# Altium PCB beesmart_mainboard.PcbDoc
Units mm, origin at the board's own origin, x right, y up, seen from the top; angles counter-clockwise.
Board outline 27.5 x 70 mm, 2 copper layers (Top Layer, Bottom Layer); 29 components, 23 nets, 160 pads, 144 vias.
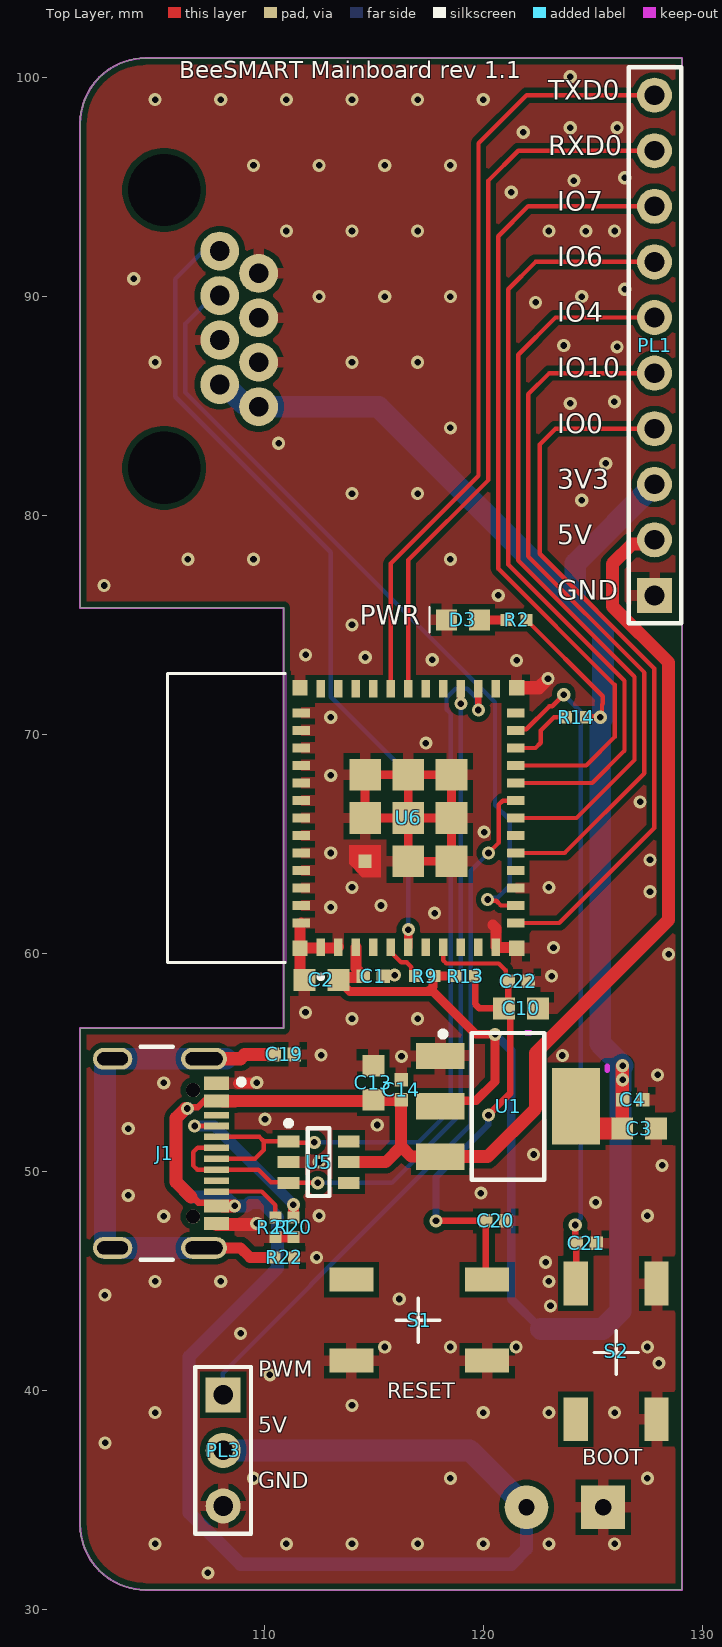
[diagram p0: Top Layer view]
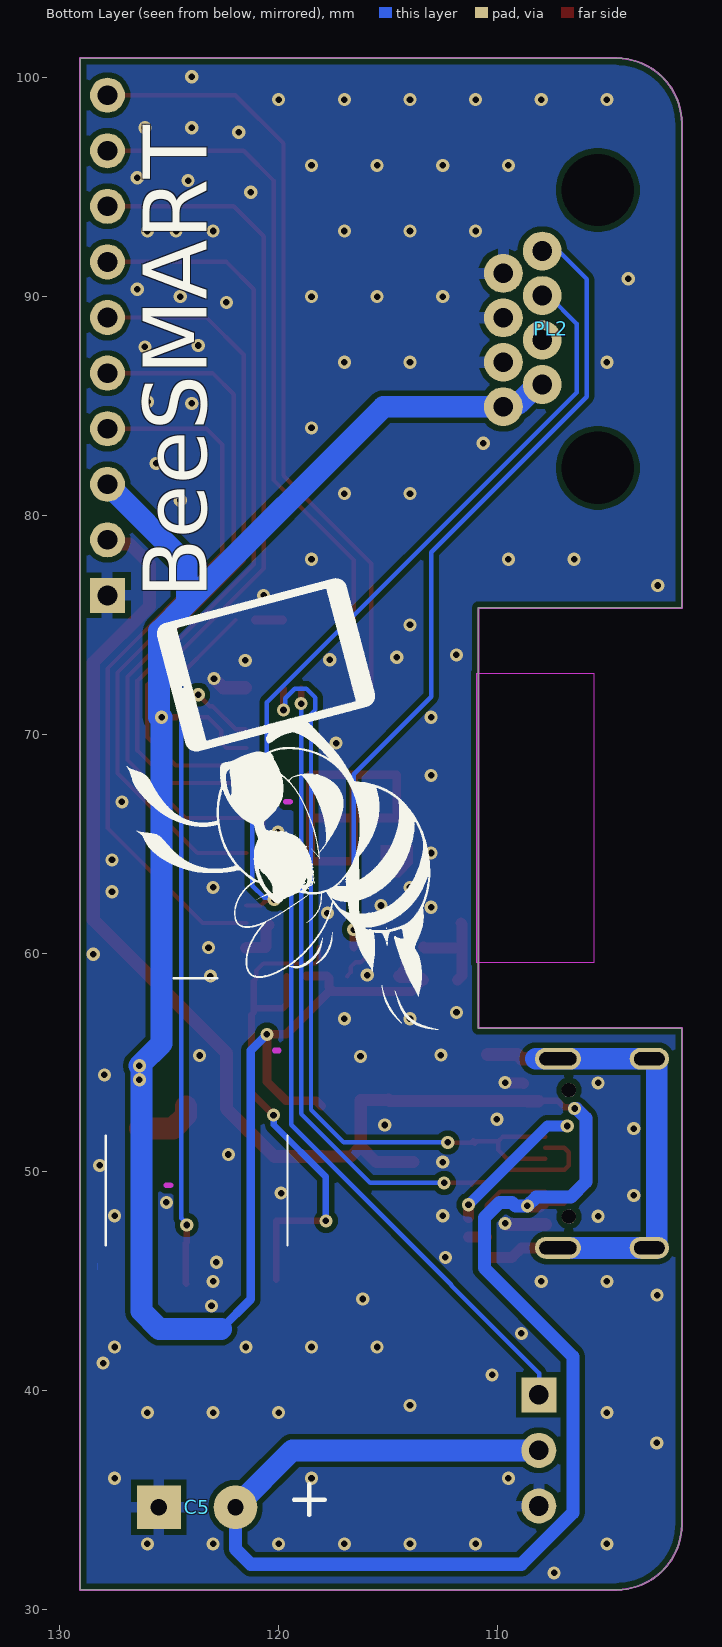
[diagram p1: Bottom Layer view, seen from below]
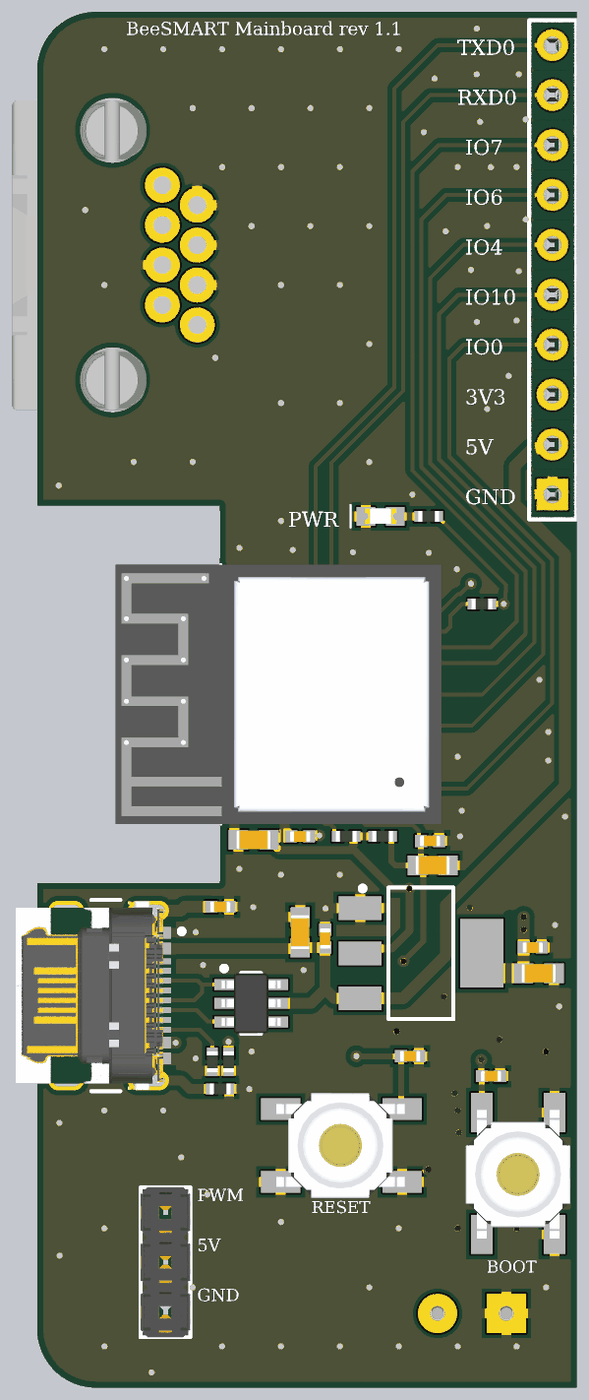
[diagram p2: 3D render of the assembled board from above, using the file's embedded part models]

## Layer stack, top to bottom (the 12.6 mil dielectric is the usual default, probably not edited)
Top Solder: solder mask 0.0102, Solder Resist, Dk 3.5
Top Layer: signal copper 0.0356
Dielectric 1: dielectric 0.32, FR-4, Dk 4.8
Bottom Layer: signal copper 0.0356
Bottom Solder: solder mask 0.0102, Solder Resist, Dk 3.5

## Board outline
101.575,33.9 101.575,56.575 110.875,56.575 110.875,75.775 101.575,75.775 101.575,97.9 cw(c104.575,97.9) 104.575,100.9 129.075,100.9 129.075,30.9 104.575,30.9 cw(c104.575,33.9)

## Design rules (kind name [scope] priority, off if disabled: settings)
Clearance [All] p1: gap=0.254 ignorepadtopadclearanceinfootprint=FALSE except(0: Arc-Hole Track-Hole SMDPad-Hole THPad-Hole Via-Hole Fill-Hole Poly-Hole Region-Hole Text-Hole; 0.2: Arc-SMDPad Arc-THPad Track-SMDPad Track-THPad SMDPad-SMDPad SMDPad-THPad)
PlaneConnect [All] p1: planeconnectstyle=Relief reliefexpansion=0.508 reliefentries=4 reliefconductorwidth=0.5 reliefairgap=0.254
PolygonConnect PolygonConnect_2 [IsVia] p1: connectstyle=Direct reliefconductorwidth=0.254 reliefentries=4 polygonreliefangle="90 Angle" airgapwidth=0.254
PolygonConnect PolygonConnect_1 [(InNet('VBUS') OR InNet('NetF1_2'))] p2: connectstyle=Direct reliefconductorwidth=0.254 reliefentries=4 polygonreliefangle="90 Angle" airgapwidth=0.254
PolygonConnect [All] p3: connectstyle=Relief reliefconductorwidth=0.5 reliefentries=4 polygonreliefangle="90 Angle" airgapwidth=0.254
RoutingVias [All] p1: holewidth=0.711 width=1.27 viastyle="Through Hole" minholewidth=0.711 minwidth=1.27 maxholewidth=0.711 maxwidth=1.27
SolderMaskExpansion [All] p1: expansion=0.102 istentingtop=FALSE
Width [All] p1: maxlimit=1 minlimit=0.2 preferedwidth=0.25 minimp=50.000000 maximp=50.000000 favimp=50.000000
29 further rules are at their usual default settings.

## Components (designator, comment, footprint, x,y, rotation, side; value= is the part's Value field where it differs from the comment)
C1 "0.1uF 0402 10V" CAP_0402 114.975,58.95 r180 top value="100 nF"
C2 "22uF 0603" CAP_0603 112.6,58.775 r0 top value=22uF
C3 "22uF 0603" CAP_0603 127.125,51.984 r180 top value=22uF
C4 "0.1uF 0402 10V" CAP_0402 126.825,53.3 r180 top value="100 nF"
C5 "180uF" "Capacitor 8x22" 123.725,34.675 r180 bottom
C10 "22uF 0603" CAP_0603 121.725,57.475 r180 top value=22uF
C13 "22uF 0603" CAP_0603 114.975,54.075 r270 top value=22uF
C14 "0.1uF 0402 10V" CAP_0402 116.25,53.75 r270 top value="100 nF"
C19 "47pF 0402 50V" CAP_0402 110.906,55.367 r180 top value=47pF
C20 "0.1uF 0402 10V" CAP_0402 120.575,47.763 r180 top value="100 nF"
C21 "0.1uF 0402 10V" CAP_0402 124.7,46.75 r180 top value="100 nF"
C22 "0.1uF 0402 10V" CAP_0402 121.591,58.716 r0 top value="100 nF"
D3 "GREEN LED 0603" "0603 LED" 103.069,68.24 r0 top
J1 "USB4105-GF-A" FP-USB4105-GF-A-MFG 104.225,50.85 r270 top
PL1 "10-pin Male Header 2.54mm" "10-pin 2.54mm header" 127.825,87.775 r90 top
PL2 "RJHSE-5080/R-RJ45R08P-A004" "AMPHENOL RJHSE-5080" 107.575,88.525 r90 bottom
PL3 "3-pin 2.54mm" "3-pin 2.54mm header" 108.112,37.275 r270 top
R2 "1k 0402" RES_0402 121.521,75.225 r0 top value=1k
R9 "10k 0.5% 0402" RES_0402 117.325,58.95 r0 top value=10k
R13 "10k 0.5% 0402" RES_0402 119.175,58.95 r180 top value=10k
R14 "10k 0.5% 0402" RES_0402 124.24,70.779 r0 top value=10k
R20 "4k7 0402" RES_0402 111.325,47.475 r90 top value=4k7
R21 "4k7 0402" RES_0402 110.5,47.475 r90 top value=4k7
R22 "1MOhm 0402 5%" RES_0402 110.9,46.1 r180 top value=1Mega
S1 "TACTB-64K-F" TACTB-64K-F 117.075,43.225 r0 top
S2 "TACTB-64K-F" TACTB-64K-F 126.075,41.8 r90 top
U1 "3.3V LDO 1A" SOT230P700X180-4N 121.131,53 r0 top
U5 "SRV05-" SOT95P280X145-6N 112.475,50.45 r0 top
U6 "ESP32-C3-MINI-1-N4" ESP32-C3-MINI-1-N4-Footprint-1 113.875,66.175 r90 top locked

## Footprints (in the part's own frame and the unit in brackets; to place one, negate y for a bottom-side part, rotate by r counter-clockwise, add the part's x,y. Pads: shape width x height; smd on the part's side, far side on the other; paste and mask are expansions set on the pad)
"3-pin 2.54mm header" [mm]
  rect 1.6x1.6 hole 0.9: 1(-2.54,0)
  round 1.6 hole 0.9: 2(0,0) 3(2.54,0)
  silkscreen extent -3.81,-1.27 3.81,1.27, body extent -3.81,-1.27 3.81,1.27, height 9.5
"10-pin 2.54mm header" [mm]
  rect 1.6x1.6 hole 0.9: 1(-11.43,0)
  round 1.6 hole 0.9: 2(-8.89,0) 3(-6.35,0) 4(-3.81,0) 5(-1.27,0) 6(1.27,0) 7(3.81,0) 8(6.35,0) 9(8.89,0) 10(11.43,0)
  silkscreen extent -12.7,-1.22 12.7,1.18, body extent -12.7,-1.24 12.7,1.25, height 8.54
"0603 LED" [mm] "0603 LED"
  rect 0.95x0.95 smd: 1(16.752,6.985) 2(15.252,6.985)
  silkscreen extent 14.48,6.43 14.48,7.57, body extent 15.2,6.61 16.8,7.39, height 0.7
"AMPHENOL RJHSE-5080" [mil] "RJ45 connector"
  round 0 hole 130 unplated: 0(-250,-85) 0(250,-85)
  round 70 hole 35.43: 1(140,15) 2(100,85) 3(60,15) 4(20,85) 5(-20,15) 6(-60,85) 7(-100,15) 8(-140,85)
  body extent -310,-286 310,304, height 521
CAP_0402 [mm] "Chip Capacitor, 2-Leads, 0402, IPC Medium Density"
  rect 0.62x0.62 smd: 1(-0.46,0) 2(0.46,0)
  body extent -0.53,-0.28 0.53,0.28, height 0.4
CAP_0603 [mm] "Chip Capacitor, 2-Leads, 0603, IPC Medium Density"
  rect 1x1 smd: 1(-0.775,0) 2(0.775,0)
  body extent -0.87,-0.48 0.87,0.48, height 0.55
"Capacitor 8x22" [mm]
  round 2 hole 0.75: 1(1.75,0)
  rect 2x2 hole 0.75: 2(-1.75,0)
  silkscreen extent -4.18,-0.35 5.82,24.18, body extent -4,-0.3 4,24, height 8.1
ESP32-C3-MINI-1-N4-Footprint-1 [mm]
  rect 0.8x0.4 smd: 1(-5.9,1.3) 2(-5.9,0.5) 3(-5.9,-0.3) 4(-5.9,-1.1) 5(-5.9,-1.9) 6(-5.9,-2.7) 7(-5.9,-3.5) 8(-5.9,-4.3) 9(-5.9,-5.1) 10(-5.9,-5.9) 11(-5.9,-6.7) 25(5.9,-6.7) 26(5.9,-5.9) 27(5.9,-5.1) 28(5.9,-4.3) 29(5.9,-3.5) 30(5.9,-2.7) 31(5.9,-1.9) 32(5.9,-1.1) 33(5.9,-0.3) 34(5.9,0.5) 35(5.9,1.3)
  rect 0.4x0.8 smd: 12(-4.8,-7.6) 13(-4,-7.6) 14(-3.2,-7.6) 15(-2.4,-7.6) 16(-1.6,-7.6) 17(-0.8,-7.6) 18(0,-7.6) 19(0.8,-7.6) 20(1.6,-7.6) 21(2.4,-7.6) 22(3.2,-7.6) 23(4,-7.6) 24(4.8,-7.6) 36(4.8,2.2) 37(4,2.2) 38(3.2,2.2) 39(2.4,2.2) 40(1.6,2.2) 41(0.8,2.2) 42(0,2.2) 43(-0.8,2.2) 44(-1.6,2.2) 45(-2.4,2.2) 46(-3.2,2.2) 47(-4,2.2) 48(-4.8,2.2)
  rect 0.6x0.6 smd paste-1 mask+0: 49_1(-1.975,-0.725)
  rect 1.45x1.45 smd: 49_2(0,-0.725) 49_3(1.975,-0.725) 49_4(1.975,-2.7) 49_5(1.975,-4.675) 49_6(0,-4.675) 49_7(-1.975,-4.675) 49_8(-1.975,-2.7) 49_9(0,-2.7)
  rect 0.7x0.7 smd: 50(5.95,2.25) 51(5.95,-7.65) 52(-5.95,-7.65) 53(-5.95,2.25)
  Top Layer region: -1.25,-1.45 -2.7,-1.45 -2.7,-0.6 -2.1,0 -1.25,0
  Keep-Out Layer region: 6.6,2.9 -6.6,2.9 -6.6,8.3 6.6,8.3
  Keep-Out Layer region: 6.6,2.9 -6.6,2.9 -6.6,8.3 6.6,8.3
  silkscreen extent -7.35,1.2 6.6,8.3, body extent -6.6,-8.3 6.6,8.3, height 2.55
FP-USB4105-GF-A-MFG [mm]
  rrect100% 1x2.1 hole 1.7 slot 0.6 at 0 deg paste-1000 mask+0: 1(-4.32,3.015) 2(4.32,3.015)
  rrect100% 1x1.8 hole 1.4 slot 0.6 at 0 deg paste-1000 mask+0: 3(-4.32,-1.165) 4(4.32,-1.165)
  round 0.65 hole 0.65 unplated paste-1000 mask+0: -(2.89,2.515) --(-2.89,2.515)
  rect 0.6x1.15 smd paste+0 mask+0: A1-B12(-3.2,3.59) A4-B9(-2.4,3.59) B1-A12(3.2,3.59) B4-A9(2.4,3.59)
  rect 0.3x1.15 smd paste+0 mask+0: A5(-1.25,3.59) A6(-0.25,3.59) A7(0.25,3.59) A8(1.25,3.59) B5(1.75,3.59) B6(0.75,3.59) B7(-0.75,3.59) B8(-1.75,3.59)
  silkscreen extent -4.86,0.11 4.86,4.84, body extent -4.96,-3.94 4.96,4.27, height 0.25
RES_0402 [mm] "Chip Resistor, 2-Leads, 0402, IPC Medium Density"
  rect 0.55x0.55 smd: 1(-0.45,0) 2(0.45,0)
  body extent -0.53,-0.28 0.53,0.28, height 0.4
SOT95P280X145-6N [mm] "SOT23, 6-Leads, Body 2.93x2.80mm, Pitch 0.95mm, IPC Medium Density"
  rect 1x0.55 smd: 1(-1.375,0.95) 2(-1.375,0) 3(-1.375,-0.95) 4(1.375,-0.95) 5(1.375,0) 6(1.375,0.95)
  silkscreen extent -1.5,-1.55 0.5,1.9, body extent -1.5,-1.53 1.5,1.53, height 1.45
SOT230P700X180-4N [mm] "SOT223, 4-Leads, Body 6,50x7,00mm (avg), Pitch 2,30mm, IPC Medium Density"
  rect 2.2x1.2 smd: 1(-3.1,2.3) 2(-3.1,0) 3(-3.1,-2.3)
  rect 2.2x3.5 smd: 2(3.1,0)
  silkscreen extent -3.1,-3.35 1.65,3.42, body extent -1.85,-3.35 1.85,3.35, height 1.8
TACTB-64K-F [mm] "Tactile switch"
  rect 2x1.1 smd: 1(-3.1,1.85) 2(3.1,1.85) 3(-3.1,-1.85) 4(3.1,-1.85)
  silkscreen extent -1.05,-1 0.95,1, body extent -3.32,-2.67 3.23,2.68, height 1.6

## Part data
C1 C4 C14 C20 C21 C22: library part CMP-00101-1, "0.1uF 0402 10V X7R 10%", Tolerance="10 %", Voltage="10 V"
C2 C3 C10 C13: library part CMP-00148-1, "Cap Ceramic 22uF 6.3V X5R 20% SMD 0603 85C Cardboard T/R", Capacitance=22uF, Case Code (Imperial)=0603, Case Code (Metric)=1608, Dielectric=X5R, Max Operating Temperature=85°C, Min Operating Temperature=-55°C, Package Quantity=1, Tolerance=20%, Voltage=6.3V
C5: library part CMP-002-0002-4, "CAP ALUM 180UF 20% 50V RADIAL", Case/Package=-, Mfg. Part Number=EEU-FR1H181LB, Tolerance=20%, Voltage=50V
C19: library part CMP-00099-1, "47pF 0402 50V X7R 5%", Tolerance=10%, Voltage=50V
D3: library part CMP-008-0000-1, "SMD GREEN WATER CLEAR", Mfg. Part Number=APT1608SGC
J1: library part CMP-003-0034-0.0, "Conn USB 2.0 Type C RCP 24 POS 0.3mm/0.5mm Solder RA SMD 24 Terminal 1 Port T/R", Flammability Rating="UL94 V-0", Insulation Color=Black, Max Operating Temperature=85°C, Min Operating Temperature=-40°C
PL1: library part CMP-003-0020-0.0, "10 Positions Header Connector 0.100\" (2.54mm) Through Hole Gold"
PL2: library part CMP-003-0022-0.1, "CONN MOD JACK 8P8C R/A UNSHLD", Colour=Black, Contact Resistance=20mR, Current Rating=1.5A, Flammability Rating="UL94 V-0", Max Operating Temperature=85°C, Max Voltage Rating (AC)=125V, Min Operating Temperature=-55°C, Package Quantity=36
PL3: library part CMP-003-0018-1, "Pin header 3-pin 2.54mm male", Mfg. Part Number=DS1021-1*3SF1-1
R2: library part CMP-001-0025-3, "RES SMD 1K OHM 1% 1/16W 0402", Case/Package=0402, Mfg. Part Number=CRG0402F1K0, Power=1/16W, Tolerance=1%
R9 R13 R14: library part CMP-0001-00029-2, "RES 10K OHM 0.5% 1/16W 0402", Case/Package=0402, Manufacturer Part No.=RC0402DR-0710KL, Tolerance=0.5%
R20 R21: library part CMP-001-0029-3, "RES SMD 4.7K OHM 1% 1/16W 0402", Case/Package=0402, Mfg. Part Number=RC1005F472CS, Power=1/16W, Tolerance=1
R22: library part CMP-001-0065-1, "RES SMD 1M OHM 5% 1/16W 0402", Case/Package=0402, Mfg. Part Number=CR0402JC1MS001, Power="1/16 W", Tolerance=5%
S1 S2: library part CMP-013-0002-1, "Microswitch TACT; SPST-NO; Positions:2; 0.05A/12VDC;", Case/Package=-
U1: library part CMP-00114-2, "IC REG LINEAR 3.3V 1A SOT223", Case/Package=TO-261-4, Dropout Voltage=1.1V, Max Input Voltage=13V, Max Operating Temperature=125°C, Max Output Current=1A, Min Operating Temperature=-40°C, Operating Supply Current=3.5mA, Output Voltage=3.3V, Package Quantity=4000, Power Supply Rejection Ratio (PSRR)=70dB, Reference Voltage=1.262V
U5: library part CMP-016-0020-1, "SRV05 Series 4 Ch 3.5 pF 15 Vclamp Steering Diode/TVS Array Combo - SOT-23-6", Capacitance=3.5pF, Case/Package=SOT-23, Clamping Voltage=15V, Leakage Current=5uA, Max Operating Temperature=150°C, Min Operating Temperature=-55°C, Peak Pulse Current=5A, Peak Pulse Power=500W, Reverse Breakdown Voltage=6V, Reverse Standoff Voltage=5V, Test Current=1mA
U6: library part CMP-00162-1, "Bluetooth, WiFi 802.11b/g/n, Bluetooth v5.0 Transceiver Module 2.412GHz ~ 2.484GHz PCB Trace Surface Mount"

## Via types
v1: diameter 0.6, hole 0.3, Top Layer to Bottom Layer, tented both sides, 144 vias

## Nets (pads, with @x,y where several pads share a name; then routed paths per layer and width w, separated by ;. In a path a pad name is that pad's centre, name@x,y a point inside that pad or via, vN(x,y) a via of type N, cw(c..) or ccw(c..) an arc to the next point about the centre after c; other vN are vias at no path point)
3V3: C1.2 C2.2 C3.2 C4.2 PL1.3 PL2.7 PL2.8 R2.2 R9.2 R13.2 R14.2 U1.2 U6.3 | length 109
  Top Layer w0.2: R2.2 125.463,71.733 125.463,71.403 125.424,71.364 125.424,70.856 v1(125.347,70.779)
  Top Layer w0.3: R14.2 v1(125.347,70.779)
  Top Layer w0.4: C2.2 113.91,58.24 117.466,58.24 ; U1.2@118.031,53 118.281,53.25 119.661,53.25 120.537,54.126 v1(120.537,56.289) 119.661,56.289 117.71,58.24 117.466,58.24 ; R13.2 R9.2 117.7,58.875 117.7,58.474 117.466,58.24
  Top Layer w0.5: C2.2 113.49,58.89 114.455,58.89 C1.2 114.175,59.29 U6.3
  Top Layer w0.6: C3.2 126.35,54.835 v1(126.365,54.85)
  Top Layer w1: U1.2@124.231,53 124.231,52.584 124.831,51.984 C3.2
  Bottom Layer w0.4: v1(120.537,56.289) 121.275,55.551 121.275,44.182 122.637,42.82
  Bottom Layer w1: PL2.7 108.167,85.985 109.034,85.118 109.585,85.118 PL2.8 115.206,84.969 124.2,75.975 ; 122.637,42.82 125.445,42.82 126.275,43.65 v1@126.275,54.85 ; v1(125.347,70.779) 125.347,55.868 v1(126.365,54.85) ; v1@125.463,70.779 125.463,74.712 124.2,75.975 ; PL1.3 124.2,77.8 124.2,75.975
  other v1: 126.365,54.21
D+: J1.A6 J1.B6 U5.3 U6.27 | length 35.2
  Top Layer w0.2: J1.A6 106.945,51.1 106.74,50.895 106.74,50.297 106.937,50.1 J1.B6 108.815,50.1 108.818,50.103 109.722,50.103 110.3,49.525 111.075,49.525 U5.3 ; U5.3@111.187,49.413 U5.3 ; v1(112.437,49.5) U5.3
  Top Layer w0.3: v1(118.975,71.4) U6.27
  Bottom Layer w0.2: v1(112.437,49.5) 115.821,49.5 118.975,52.654 v1(118.975,71.4)
D-: J1.A7 J1.B7 U5.1 U6.26 | length 36.5
  Top Layer w0.2: J1.A7 109.568,50.6 109.971,51.003 109.971,51.4 ; J1.B7 109.771,51.6 109.971,51.4 ; U5.1@111.032,51.332 v1@112.275,51.332 ; U5.1@111.108,51.392 U5.1 109.971,51.4
  Top Layer w0.3: U5.1@111.032,51.332 U5.1 ; U6.26 119.779,72.071 v1(119.779,71.111)
  Bottom Layer w0.2: v1(112.275,51.35) 117.029,51.35 118.521,52.842 118.521,70.929 118.321,71.129 118.321,71.671 118.735,72.084 119.269,72.084 119.702,71.651 119.702,71.187 v1(119.779,71.111)
ENA: C10.2 C20.2 C22.1 R13.1 S1.2 U6.8 | length 24.3
  Top Layer w0.2: U6.8 118.175,59.665 118.315,59.525 120.71,59.525 121.026,59.209 121.026,58.821 C22.1
  Top Layer w0.3: v1(117.84,47.763) C20.2 S1.2@120.115,45.075 ; R13.1 119.625,57.676 119.826,57.475 C10.2 ; v1(120.238,52.6) 121.241,53.603 121.241,57.184 121.131,57.294 C22.1
  Bottom Layer w0.3: v1@117.84,47.723 117.84,49.769 120.224,52.153 120.224,52.586 v1(120.238,52.6)
GND: C1.1 C2.1 C3.1 C4.1 C5.2 C10.1 C13.1 C14.1 C19.1 C20.1 C21.1 C22.2 D3.2 J1.A1-B12 J1.B1-A12 PL1.1 PL2.2 PL2.4 PL2.5 PL2.6 PL3.3 R20.1 R21.1 R22.1 S1.3 S1.4 S2.3 S2.4 U1.1 U5.2 U6.1 U6.2 U6.11 U6.14 U6.36 U6.37 U6.38 U6.39 U6.40 U6.41 U6.42 U6.43 U6.44 U6.45 U6.46 U6.47 U6.48 U6.49_1 U6.49_2 U6.49_3 U6.49_4 U6.49_5 U6.49_6 U6.49_7 U6.49_8 U6.49_9 U6.50 U6.51 U6.52 U6.53 | length 31.4
  Top Layer w0.4: U6.49_9 U6.49_8 U6.49_7 U6.49_6 ; U6.49_9 U6.49_2 U6.49_3 U6.49_4 ; U6.49_9 U6.49_6 ; U6.49_9 U6.49_4 ; U6.49_4 U6.49_5 U6.49_6
  Top Layer w0.5: 108.815,54.05 108.83,54.065 109.635,54.065 v1(109.65,54.079) ; R21.1 R20.1 ; U6.48 111.625,61.325 U6.53 ; C2.1 111.625,58.975 U6.53 ; U6.2 113.325,60.225 U6.53 ; 120.431,61.279 120.575,61.135 U6.11 ; U6.11@120.6,60.25 121.5,60.25 U6.52
  Top Layer w0.6: J1.B1-A12@107.815,47.592 109.592,47.592 v1(109.65,47.65) ; U6.51 122.536,72.125 v1(122.957,72.546)
  other v1: 107.412,31.676 105,33 111,33 114,33 117,33 120,33 123,33 126,33 109.5,36 118.5,36 127.5,36 102.721,37.618 105,39 120,39 123,39 126,39 114,39.329 110.25,40.725 128.025,41.262 115.5,42 118.5,42 121.5,42 127.5,42 108.907,42.623 123.07,43.88 116.158,44.194 102.71,44.374 105,45 108,45 123,45 122.85,45.871 112.385,46.096 105.4,47.976 112.5,48 127.5,48 125.13,48.61 103.775,48.925 119.889,49.03 128.175,50.297 112.5,50.45 122.301,50.796 103.775,51.984 115.154,52.146 110.026,52.407 105.4,54.068 127.964,54.435 116.261,55.28 123.613,55.32 112.589,55.341 114,57 117,57 111.875,57.294 123.123,58.95 115.951,58.994 128.471,59.951 123.208,60.25 117.775,61.829 113.032,62.095 115.325,62.175 127.617,62.804 114,63 123,63 127.617,64.261 113.032,64.575 120.035,65.531 127.163,66.914 113.032,68.121 117.375,69.598 113.032,70.779 121.525,73.377 117.666,73.405 114.604,73.52 111.879,73.625 114,75 120.687,76.345 102.675,76.8 106.5,78 109.5,78 118.5,78 124.5,80.695 114,81 117,81 125.595,82.378 110.649,83.301 118.5,84 123.972,85.119 125.994,85.196 105,87 114,87 117,87 126.117,87.703 123.677,87.767 122.388,89.735 112.5,90 115.5,90 118.5,90 124.5,90 126.465,90.337 104.025,90.815 111,93 114,93 117,93 123,93 124.69,92.996 126,93 121.275,94.772 124.14,95.303 126.465,95.431 109.5,96 112.5,96 115.5,96 118.5,96 121.826,97.508 123.972,97.719 126.117,97.719 105,99 108,99 111,99 114,99 117,99 120,99 123.972,100.048
IO0: PL1.4 U6.12 | length 33.4
  Top Layer w0.2: U6.12 123.475,61.375 127.817,65.717 127.817,73.008 122.575,78.25 122.575,83.24 123.3,83.965 PL1.4
IO1: PL2.3 U6.13 | length 36.6
  Top Layer w0.2: v1(120.2,62.45) 120.259,62.391 120.59,62.391 120.806,62.175 U6.13
  Bottom Layer w0.2: PL2.3 107.675,90.049 106.379,88.753 106.379,85.616 120.537,71.458 120.537,66.763 121.204,66.096 121.204,63.079 120.651,62.527 120.277,62.527 v1(120.2,62.45)
IO3: PL2.1 U6.6 | length 37.5
  Top Layer w0.4: U6.6 v1(116.575,61.075)
  Bottom Layer w0.2: PL2.1 107.206,92.081 105.925,90.8 105.925,85.428 113.032,78.322 113.032,71.718 116.575,68.175 v1(116.575,61.075)
IO4: PL1.6 U6.18 | length 34.2
  Top Layer w0.2: U6.18 124.258,66.175 126.909,68.826 126.909,72.632 121.595,77.946 121.595,87.34 123.3,89.045 PL1.6
IO5: PL3.1 U6.19 | length 32.7
  Top Layer w0.2: v1(120.238,64.575) 120.7,65.037 120.7,66.775 120.892,66.968 121.468,66.968 U6.19
  Bottom Layer w0.2: PL3.1@108.1,40.125 108.1,40.803 112.112,44.815 112.112,44.843 119.429,52.159 119.429,63.766 v1(120.238,64.575)
IO6: PL1.7 U6.20 | length 36.1
  Top Layer w0.2: U6.20 124.975,67.775 126.455,69.255 126.455,72.444 121.141,77.758 121.141,90.337 122.388,91.585 PL1.7
IO7: PL1.8 U6.21 | length 37.9
  Top Layer w0.2: U6.21 124.7,68.575 126.001,69.876 126.001,72.256 120.687,77.57 120.687,92.763 122.049,94.125 PL1.8
IO9: C21.2 S2.2 U6.23 | length 30.2
  Top Layer w0.2: U6.23 121.525,70.225 121.962,70.225 123.02,71.283 123.152,71.283 v1(123.677,71.808)
  Top Layer w0.3: v1(124.2,47.575) 124.2,46.79 C21.2 124.24,44.915 S2.2
  Bottom Layer w0.2: v1(123.677,71.808) 124.455,71.031 124.455,47.892 124.2,47.637 v1(124.2,47.575)
IO10: PL1.5 U6.16 | length 33.1
  Top Layer w0.2: U6.16 123.717,64.575 127.363,68.221 127.363,72.82 122.049,78.134 122.049,85.533 123.02,86.505 PL1.5
NetC19_2: C19.2 J1.1 J1.2 J1.3 J1.4 R22.2 | length 23.4
  Top Layer w0.5: J1.2@108.24,46.53 108.903,46.53 109.333,46.1 R22.2 R22.2@110.446,46.096
  Top Layer w0.6: J1.1@108.24,55.17 108.898,55.17 109.095,55.367 C19.2
  Bottom Layer w1: J1.2 102.721,46.53 102.721,55.17 J1.1 J1.1@108.24,55.17
NetD3_1: D3.1 R2.1 | length 1.3
  Top Layer w0.4: D3.1 R2.1
NetJ1_A5: J1.A5 R20.2 | length 7.6
  Top Layer w0.25: v1(106.811,52.1) J1.A5
  Top Layer w0.5: R20.2 v1(111.325,48.5)
  Bottom Layer w0.5: v1(106.811,52.1) 107.725,52.1 v1(111.325,48.5)
NetJ1_B5: J1.B5 R21.2 | length 3.5
  Top Layer w0.2: J1.B5 107.819,49.104 109.871,49.104 110.5,48.475 R21.2
NetR9_1: R9.1 U6.5 | length 1.9
  Top Layer w0.2: U6.5 115.875,60.175 115.875,59.951 116.251,59.575 116.5,59.575 116.713,59.362 116.713,59.112 R9.1
NetR14_1: R14.1 U6.22 | length 3.2
  Top Layer w0.2: U6.22 122.388,69.375 122.625,69.612 122.625,70.175 123.229,70.779 R14.1
RXD0: PL1.9 U6.30 | length 32.9
  Top Layer w0.2: U6.30 116.575,77.965 120.233,81.622 120.233,95.303 121.595,96.665 PL1.9
TXD0: PL1.10 U6.31 | length 35.5
  Top Layer w0.2: U6.31 115.775,77.807 119.779,81.81 119.779,94.854 119.779,97.004 121.98,99.205 PL1.10
VCC: C5.1 C13.2 C14.2 J1.A4-B9 J1.B4-A9 PL1.2 PL3.2 U1.3 U5.5 | length 118.2
  Top Layer w0.3: v1@106.532,52.957 106.952,52.957 107.245,53.25 J1.A4-B9 J1.A4-B9@108.095,53.25 ; 106.731,48.85 106.981,48.6 J1.B4-A9@107.665,48.6 ; J1.B4-A9 107.817,48.448 108.599,48.448 108.635,48.448 v1(108.637,48.446) ; J1.A4-B9@108.095,53.1 108.665,53.1 108.815,53.25 ; v1@108.665,48.596 v1@108.669,48.596
  Top Layer w0.55: J1.A4-B9@108.095,53.25 108.815,53.25 114.925,53.25 C13.2 114.98,53.295 116.245,53.295 C14.2 116.25,51.163 ; U5.5 115.537,50.45 116.25,51.163 ; U1.3 116.713,50.7 116.25,51.163
  Top Layer w0.6: v1@106.403,52.9 105.957,52.454 105.957,49.543 106.65,48.85 ; J1.B4-A9@108.095,48.45 108.597,48.45 108.599,48.448 108.601,48.446 v1(108.637,48.446) ; U1.3 120.192,50.7 122.388,52.896 122.388,55.438 128.471,61.52 128.471,73.279 125.9,75.85 125.9,77.785 126.81,78.695 127.635,78.695 PL1.2
  Bottom Layer w0.6: v1(106.475,52.9) 106.403,52.9 105.957,52.454 105.957,49.543 106.65,48.85 108.233,48.85 v1(108.637,48.446) 109.185,48.446 109.349,48.61 109.898,48.61 110.6,47.908 110.6,45.61 106.557,41.567 106.557,34.425 108.907,32.075 121.275,32.075 121.975,32.775 C5.1
  Bottom Layer w1: PL3.2 119.375,37.275 C5.1
pads on no net: J1.- J1.-- J1.A8 J1.B8 PL2.0 S1.1 S2.1 U5.4 U5.6 U6.4 U6.7 U6.9 U6.10 U6.15 U6.17 U6.24 U6.25 U6.28 U6.29 U6.32 U6.33 U6.34 U6.35

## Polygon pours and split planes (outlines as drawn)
GND on Bottom Layer "NONET_L-01_P-001" (solid, remove dead copper, pour order 0): 131.175,27.35 132.775,28.95 132.775,104.325 96.875,104.325 92.55,100 96.425,96.125 96.425,28.175
GND on Top Layer "NONET_L-01_P-001" (solid, remove dead copper, pour order 1): 131.175,27.35 132.775,28.95 132.775,104.325 96.875,104.325 92.55,100 96.425,96.125 96.425,28.175

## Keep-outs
Top Layer:
  lines w0.254: 121.955,56.356 122.142,56.356 ; 125.665,54.647 125.665,54.833
Bottom Layer:
  lines w0.254: 119.481,66.914 119.668,66.914 ; 119.989,55.551 120.176,55.551 ; 124.943,49.39 125.13,49.39
Keep-Out Layer:
  the board outline again, w0.1

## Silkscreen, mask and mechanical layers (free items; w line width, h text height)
Top Overlay:
  text "BeeSMART Mainboard rev 1.1" at 106.1,99.725 h1.3
  text "TXD0" at 122.975,98.71 h1.5
  text "RXD0" at 122.975,96.17 h1.5
  text "IO7" at 123.375,93.63 h1.5
  text "IO6" at 123.375,91.09 h1.5
  text "IO4" at 123.375,88.55 h1.5
  text "IO10" at 123.375,86.01 h1.5
  text "IO0" at 123.375,83.47 h1.5
  text "3V3" at 123.375,80.93 h1.5
  text "5V" at 123.375,78.39 h1.5
  text "GND" at 123.375,75.85 h1.5
  text "PWR" at 114.35,74.7 h1.5
  text "PWM" at 109.725,40.38 h1.25
  text "RESET" at 115.6,39.425 h1.2
  text "5V" at 109.725,37.84 h1.25
  text "BOOT" at 124.525,36.4 h1.2
  text "GND" at 109.725,35.3 h1.25
Bottom Overlay:
  drawing of 29 lines, arcs and shapes, not listed
  text "BeeSMART" at 122.33,76.203 h5 r270
Outline:
  lines w0.1: 101.575,75.775 101.575,97.9 cw(c104.575,97.9) 104.575,100.9 129.075,100.9 129.075,30.9 104.575,30.9 cw(c104.575,33.9) 101.575,33.9 101.575,56.575 110.875,56.575 110.875,75.775 101.575,75.775 ; 101.575,75.775 101.575,75.775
